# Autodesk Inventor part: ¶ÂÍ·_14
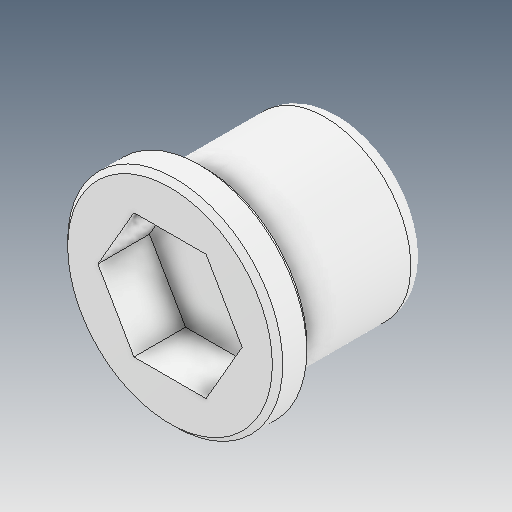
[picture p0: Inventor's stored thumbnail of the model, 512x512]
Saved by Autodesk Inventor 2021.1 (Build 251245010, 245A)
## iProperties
Created: 2021-06
Part Number: ¶ÂÍ·_14
Material: Ogólny
Document SubType Name: Modeling
Designer: user
Density: 1 g/cm^3
Appearance: Domyślna
Author: user
Revision Number: ÈÎºÎ
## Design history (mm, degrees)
feature "ÊäÈë1"
node "Bryła1"
